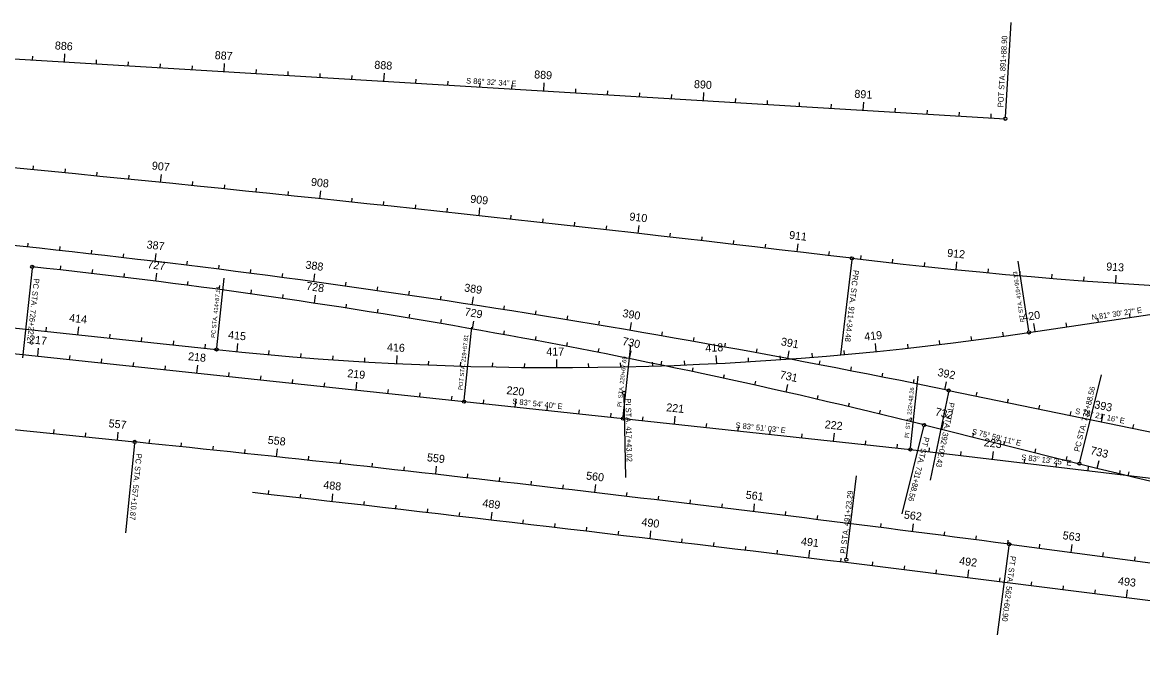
# Model space of a CAD drawing. Extents: x 919452 to 931278, y 583254 to 665650.
# Drawn here: x 927014 to 927714, y 636499 to 636895 of the extents above; entities that cross this region are included whole.
import ezdxf

# ---------------------------------------------------------------- set-up
doc = ezdxf.new("R2010")
doc.units = 0
for name, color, linetype in [('CLConst_dp', 7, 'Continuous'), ('CurveDataLabel_dp', 7, 'Continuous'), ('StationTicL_dp', 7, 'Continuous'), ('StationTicS_dp', 7, 'Continuous'), ('TextBLStation', 7, 'Continuous'), ('TextLabel', 7, 'Continuous')]:
    doc.layers.add(name, color=color, linetype=linetype)

msp = doc.modelspace()

# ---------------------------------------------------------------- linework, layer by layer
at = {"layer": 'CLConst_dp'}
for p, q in [((926993.81, 636873.2), (927628.09, 636834.88)), ((926652.85, 636742.2), (927135.36, 636690.73)), ((926651.16, 636726.29), (927289.95, 636658.15)), ((927642.87, 636701.38), (927761.55, 636719.1)), ((926620.06, 636680.55), (927084.21, 636632.96)), ((927592.72, 636665.12), (927788.61, 636624.75)), ((927289.95, 636658.15), (927389.26, 636647.56)), ((927389.26, 636647.56), (927568.79, 636628.21)), ((927577.33, 636643.56), (927674.36, 636619.34)), ((927568.79, 636628.21), (927746.27, 636607.13)), ((927630.5, 636569.05), (928164.62, 636498.82))]:
    msp.add_line(p, q, dxfattribs=at)
for centre, radius, start, end in [((924808.61, 613941.45), 22968.31, 83.189634, 85.623449), ((926386.43, 630812.14), 5976, 78.354474, 84.656985), ((927919.83, 639992.88), 3268.24, 263.18963, 272.20538), ((926584.51, 632665.58), 4100, 75.98637, 83.89999), ((927347.51, 638679.45), 2000, 263.91108, 278.49255), ((925121.35, 617487.67), 19245.65, 82.508751, 84.146229), ((928618.75, 640403.27), 3900, 255.98637, 261.64217), ((922956.96, 599413.81), 37423.99, 82.411957, 83.554939)]:
    msp.add_arc(centre, radius, start, end, dxfattribs=at)
at = {"layer": 'CurveDataLabel_dp'}
for p, q in [((927628.15, 636835.87), (927631.73, 636895.12)), ((927532.16, 636746.7), (927525.07, 636687.36)), ((927642.72, 636702.37), (927636.23, 636745.83)), ((927020.08, 636741.37), (927014.11, 636685.5)), ((927135.47, 636691.73), (927140.13, 636735.38)), ((927290.06, 636659.14), (927294.92, 636704.74)), ((927389.37, 636648.55), (927394.15, 636693.33)), ((927674.6, 636620.31), (927688.23, 636674.91)), ((927568.9, 636629.21), (927573.72, 636673.98)), ((927389.82, 636662.59), (927390.9, 636610.77)), ((927592.52, 636664.14), (927581.17, 636609.04)), ((927577.09, 636642.59), (927563.49, 636588.08)), ((927084.11, 636631.97), (927078.38, 636576.07)), ((927528.88, 636560.37), (927535.2, 636611.74)), ((927630.37, 636568.06), (927623.04, 636512.38))]:
    msp.add_line(p, q, dxfattribs=at)
for centre in [(927628.09, 636834.88), (927532.27, 636747.7), (927020.19, 636742.37), (927642.87, 636701.38), (927135.36, 636690.73), (927389.8, 636663.59), (927592.72, 636665.12), (927289.95, 636658.15), (927389.26, 636647.56), (927577.33, 636643.56), (927084.21, 636632.96), (927568.79, 636628.21), (927674.36, 636619.34), (927630.5, 636569.05), (927528.76, 636559.38)]:
    msp.add_circle(centre, 1, dxfattribs=at)
at = {"layer": 'StationTicL_dp'}
for p, q in [((927040.27, 636870.39), (927040.57, 636875.38)), ((927140.09, 636864.36), (927140.39, 636869.35)), ((927239.91, 636858.33), (927240.21, 636863.32)), ((927339.72, 636852.3), (927340.02, 636857.29)), ((927439.54, 636846.27), (927439.84, 636851.26)), ((927539.36, 636840.24), (927539.66, 636845.23)), ((927100.4, 636795.14), (927100.9, 636800.11)), ((927199.88, 636784.94), (927200.4, 636789.91)), ((927299.31, 636774.31), (927299.85, 636779.28)), ((927398.7, 636763.25), (927399.26, 636768.22)), ((927498.03, 636751.76), (927498.62, 636756.73)), ((927096.96, 636745.75), (927097.55, 636750.71)), ((927597.41, 636740.58), (927597.9, 636745.56)), ((927097.4, 636733.38), (927098.02, 636738.34)), ((927196.14, 636733.03), (927196.82, 636737.98)), ((927697.05, 636732.24), (927697.39, 636737.23)), ((927196.45, 636719.66), (927197.2, 636724.6)), ((927295.1, 636718.65), (927295.86, 636723.59)), ((927048.71, 636699.98), (927049.24, 636704.95)), ((927295.14, 636703.53), (927296, 636708.45)), ((927393.81, 636702.62), (927394.65, 636707.55)), ((927646.69, 636701.95), (927645.96, 636706.9)), ((927023.65, 636686.56), (927024.18, 636691.53)), ((927148.15, 636689.41), (927148.65, 636694.38)), ((927393.4, 636685), (927394.39, 636689.9)), ((927492.23, 636684.94), (927493.16, 636689.85)), ((927547.49, 636689.47), (927546.99, 636694.45)), ((927247.86, 636681.93), (927248.11, 636686.93)), ((927347.82, 636679.45), (927347.82, 636684.45)), ((927447.78, 636681.96), (927447.53, 636686.96)), ((927123.09, 636675.95), (927123.62, 636680.92)), ((927222.52, 636665.34), (927223.05, 636670.32)), ((927491.19, 636664.07), (927492.29, 636668.95)), ((927590.34, 636665.61), (927591.35, 636670.51)), ((927321.96, 636654.74), (927322.49, 636659.71)), ((927421.39, 636644.1), (927421.92, 636649.07)), ((927688.29, 636645.43), (927689.3, 636650.32)), ((927588.44, 636640.79), (927589.65, 636645.64)), ((927073.4, 636634.07), (927073.91, 636639.04)), ((927520.81, 636633.38), (927521.35, 636638.36)), ((927172.86, 636623.67), (927173.39, 636628.64)), ((927620.17, 636622.11), (927620.76, 636627.07)), ((927685.46, 636616.59), (927686.66, 636621.44)), ((927272.26, 636612.75), (927272.82, 636617.72)), ((927371.6, 636601.31), (927372.19, 636606.28)), ((927207.5, 636595.63), (927208.07, 636600.6)), ((927470.89, 636589.36), (927471.5, 636594.33)), ((927306.84, 636584.14), (927307.42, 636589.11)), ((927406.15, 636572.39), (927406.74, 636577.35)), ((927570.11, 636576.9), (927570.74, 636581.86)), ((927505.42, 636560.37), (927506.03, 636565.33)), ((927669.26, 636563.96), (927669.92, 636568.91)), ((927604.67, 636548.08), (927605.29, 636553.04)), ((927703.87, 636535.53), (927704.51, 636540.49))]:
    msp.add_line(p, q, dxfattribs=at)
at = {"layer": 'StationTicS_dp'}
for p, q in [((927020.31, 636871.59), (927020.46, 636874.09)), ((927060.23, 636869.18), (927060.38, 636871.68)), ((927080.2, 636867.98), (927080.35, 636870.47)), ((927100.16, 636866.77), (927100.31, 636869.27)), ((927120.12, 636865.56), (927120.27, 636868.06)), ((927160.05, 636863.15), (927160.2, 636865.65)), ((927180.01, 636861.95), (927180.17, 636864.44)), ((927199.98, 636860.74), (927200.13, 636863.24)), ((927219.94, 636859.53), (927220.09, 636862.03)), ((927259.87, 636857.12), (927260.02, 636859.62)), ((927279.83, 636855.92), (927279.98, 636858.41)), ((927299.8, 636854.71), (927299.95, 636857.2)), ((927319.76, 636853.5), (927319.91, 636856)), ((927359.69, 636851.09), (927359.84, 636853.59)), ((927379.65, 636849.89), (927379.8, 636852.38)), ((927399.61, 636848.68), (927399.76, 636851.17)), ((927419.58, 636847.47), (927419.73, 636849.97)), ((927459.5, 636845.06), (927459.66, 636847.56)), ((927479.47, 636843.85), (927479.62, 636846.35)), ((927499.43, 636842.65), (927499.58, 636845.14)), ((927519.4, 636841.44), (927519.55, 636843.94)), ((927559.32, 636839.03), (927559.47, 636841.53)), ((927579.29, 636837.82), (927579.44, 636840.32)), ((927599.25, 636836.62), (927599.4, 636839.11)), ((927619.21, 636835.41), (927619.36, 636837.91)), ((927020.78, 636802.98), (927021.02, 636805.47)), ((927040.69, 636801.04), (927040.93, 636803.53)), ((927060.59, 636799.09), (927060.84, 636801.58)), ((927080.5, 636797.12), (927080.74, 636799.61)), ((927120.3, 636793.13), (927120.55, 636795.62)), ((927140.2, 636791.11), (927140.45, 636793.6)), ((927160.09, 636789.07), (927160.35, 636791.56)), ((927179.99, 636787.01), (927180.24, 636789.5)), ((927219.77, 636782.85), (927220.03, 636785.34)), ((927239.66, 636780.74), (927239.92, 636783.23)), ((927259.54, 636778.62), (927259.81, 636781.1)), ((927279.43, 636776.47), (927279.7, 636778.96)), ((927319.19, 636772.14), (927319.47, 636774.62)), ((927339.07, 636769.94), (927339.35, 636772.43)), ((927358.95, 636767.73), (927359.23, 636770.21)), ((927378.82, 636765.5), (927379.1, 636767.98)), ((927418.57, 636760.99), (927418.85, 636763.47)), ((927438.44, 636758.71), (927438.72, 636761.19)), ((927458.31, 636756.41), (927458.59, 636758.89)), ((927017.46, 636754.73), (927017.73, 636757.21)), ((927037.35, 636752.58), (927037.62, 636755.07)), ((927057.22, 636750.37), (927057.5, 636752.85)), ((927478.17, 636754.09), (927478.46, 636756.58)), ((927517.9, 636749.41), (927518.19, 636751.89)), ((927077.09, 636748.09), (927077.38, 636750.58)), ((927116.81, 636743.34), (927117.12, 636745.82)), ((927537.76, 636747.05), (927538.05, 636749.53)), ((927557.63, 636744.77), (927557.9, 636747.25)), ((927577.51, 636742.61), (927577.77, 636745.1)), ((927037.82, 636740.45), (927038.09, 636742.93)), ((927057.69, 636738.19), (927057.98, 636740.67)), ((927077.55, 636735.83), (927077.85, 636738.31)), ((927136.66, 636740.86), (927136.97, 636743.34)), ((927156.49, 636738.32), (927156.82, 636740.79)), ((927176.32, 636735.7), (927176.65, 636738.18)), ((927617.31, 636738.67), (927617.55, 636741.16)), ((927637.23, 636736.88), (927637.45, 636739.37)), ((927657.16, 636735.21), (927657.37, 636737.7)), ((927117.23, 636730.83), (927117.56, 636733.31)), ((927137.06, 636728.18), (927137.4, 636730.66)), ((927215.95, 636730.28), (927216.3, 636732.76)), ((927677.1, 636733.66), (927677.29, 636736.16)), ((927156.87, 636725.44), (927157.22, 636727.91)), ((927176.67, 636722.6), (927177.03, 636725.07)), ((927235.76, 636727.48), (927236.11, 636729.95)), ((927255.55, 636724.6), (927255.91, 636727.07)), ((927275.33, 636721.66), (927275.7, 636724.13)), ((927216.22, 636716.63), (927216.6, 636719.1)), ((927314.86, 636715.58), (927315.25, 636718.05)), ((927235.97, 636713.5), (927236.37, 636715.96)), ((927255.71, 636710.27), (927256.12, 636712.74)), ((927275.43, 636706.95), (927275.85, 636709.41)), ((927334.62, 636712.44), (927335.01, 636714.9)), ((927354.36, 636709.23), (927354.76, 636711.7)), ((927686.26, 636707.86), (927685.89, 636710.33)), ((927706.04, 636710.81), (927705.67, 636713.28)), ((927028.83, 636702.1), (927029.09, 636704.58)), ((927314.83, 636700.01), (927315.27, 636702.47)), ((927374.09, 636705.96), (927374.5, 636708.42)), ((927666.48, 636704.9), (927666.11, 636707.38)), ((927068.6, 636697.85), (927068.87, 636700.34)), ((927088.49, 636695.73), (927088.75, 636698.22)), ((927108.37, 636693.61), (927108.64, 636696.1)), ((927334.5, 636696.4), (927334.96, 636698.86)), ((927354.15, 636692.7), (927354.62, 636695.15)), ((927413.52, 636699.21), (927413.95, 636701.68)), ((927433.21, 636695.74), (927433.65, 636698.21)), ((927587.24, 636693.87), (927586.94, 636696.35)), ((927607.09, 636696.37), (927606.76, 636698.84)), ((927626.9, 636699.06), (927626.56, 636701.54)), ((927128.26, 636691.49), (927128.53, 636693.98)), ((927168.06, 636687.52), (927168.29, 636690)), ((927187.99, 636685.82), (927188.19, 636688.31)), ((927373.79, 636688.9), (927374.27, 636691.35)), ((927452.9, 636692.21), (927453.34, 636694.67)), ((927472.57, 636688.61), (927473.02, 636691.06)), ((927507.65, 636685.87), (927507.45, 636688.36)), ((927527.58, 636687.57), (927527.35, 636690.06)), ((927567.38, 636691.57), (927567.1, 636694.06)), ((927043.54, 636684.44), (927043.8, 636686.92)), ((927063.42, 636682.32), (927063.69, 636684.8)), ((927083.31, 636680.19), (927083.58, 636682.68)), ((927207.94, 636684.32), (927208.11, 636686.82)), ((927227.89, 636683.03), (927228.04, 636685.52)), ((927267.84, 636681.04), (927267.94, 636683.53)), ((927287.83, 636680.34), (927287.91, 636682.84)), ((927307.82, 636679.84), (927307.87, 636682.34)), ((927327.82, 636679.55), (927327.85, 636682.05)), ((927367.82, 636679.55), (927367.8, 636682.05)), ((927387.82, 636679.86), (927387.77, 636682.35)), ((927407.81, 636680.36), (927407.74, 636682.86)), ((927413, 636681), (927413.51, 636683.45)), ((927427.8, 636681.06), (927427.7, 636683.56)), ((927467.75, 636683.07), (927467.6, 636685.56)), ((927487.71, 636684.37), (927487.53, 636686.86)), ((927511.88, 636681.2), (927512.35, 636683.66)), ((927103.2, 636678.07), (927103.46, 636680.56)), ((927142.97, 636673.83), (927143.24, 636676.32)), ((927162.86, 636671.71), (927163.12, 636674.19)), ((927432.58, 636676.91), (927433.09, 636679.36)), ((927452.14, 636672.73), (927452.66, 636675.17)), ((927531.52, 636677.4), (927531.99, 636679.86)), ((927551.14, 636673.54), (927551.63, 636675.99)), ((927182.75, 636669.59), (927183.01, 636672.07)), ((927202.63, 636667.47), (927202.9, 636669.95)), ((927471.67, 636668.45), (927472.21, 636670.89)), ((927570.75, 636669.61), (927571.24, 636672.06)), ((927242.41, 636663.22), (927242.67, 636665.71)), ((927262.3, 636661.1), (927262.56, 636663.59)), ((927282.18, 636658.98), (927282.45, 636661.47)), ((927510.68, 636659.6), (927511.25, 636662.04)), ((927609.93, 636661.58), (927610.44, 636664.02)), ((927302.07, 636656.86), (927302.33, 636659.34)), ((927341.84, 636652.61), (927342.11, 636655.1)), ((927530.15, 636655.04), (927530.73, 636657.47)), ((927629.52, 636657.54), (927630.03, 636659.99)), ((927649.11, 636653.5), (927649.61, 636655.95)), ((927361.73, 636650.49), (927362, 636652.98)), ((927381.62, 636648.37), (927381.88, 636650.86)), ((927401.5, 636646.24), (927401.77, 636648.72)), ((927549.6, 636650.38), (927550.19, 636652.81)), ((927569.03, 636645.62), (927569.63, 636648.05)), ((927668.7, 636649.46), (927669.2, 636651.91)), ((927033.61, 636638.15), (927033.86, 636640.64)), ((927441.27, 636641.95), (927441.54, 636644.44)), ((927461.16, 636639.81), (927461.43, 636642.3)), ((927481.04, 636637.67), (927481.31, 636640.15)), ((927707.87, 636641.39), (927708.38, 636643.84)), ((927053.5, 636636.11), (927053.76, 636638.6)), ((927093.3, 636632.03), (927093.55, 636634.52)), ((927113.19, 636629.97), (927113.45, 636632.46)), ((927500.93, 636635.53), (927501.2, 636638.01)), ((927540.7, 636631.24), (927540.97, 636633.73)), ((927607.84, 636635.95), (927608.45, 636638.37)), ((927627.25, 636631.1), (927627.85, 636633.53)), ((927133.08, 636627.89), (927133.34, 636630.38)), ((927152.97, 636625.79), (927153.23, 636628.27)), ((927560.58, 636629.1), (927560.85, 636631.58)), ((927580.45, 636626.83), (927580.75, 636629.31)), ((927600.31, 636624.47), (927600.61, 636626.95)), ((927646.65, 636626.26), (927647.26, 636628.69)), ((927192.74, 636621.52), (927193.01, 636624.01)), ((927212.62, 636619.36), (927212.9, 636621.85)), ((927232.5, 636617.18), (927232.78, 636619.66)), ((927640.04, 636619.75), (927640.33, 636622.23)), ((927659.9, 636617.39), (927660.19, 636619.87)), ((927666.06, 636621.42), (927666.66, 636623.84)), ((927252.38, 636614.97), (927252.66, 636617.46)), ((927292.13, 636610.5), (927292.41, 636612.99)), ((927679.76, 636615.03), (927680.05, 636617.51)), ((927699.62, 636612.67), (927699.91, 636615.15)), ((927704.9, 636611.85), (927705.48, 636614.28)), ((927312, 636608.24), (927312.29, 636610.72)), ((927331.87, 636605.95), (927332.16, 636608.43)), ((927351.74, 636603.64), (927352.03, 636606.13)), ((927167.76, 636600.16), (927168.04, 636602.64)), ((927187.63, 636597.9), (927187.92, 636600.38)), ((927391.46, 636598.97), (927391.76, 636601.45)), ((927411.32, 636596.6), (927411.62, 636599.08)), ((927227.37, 636593.36), (927227.66, 636595.84)), ((927247.24, 636591.07), (927247.53, 636593.55)), ((927267.11, 636588.77), (927267.4, 636591.25)), ((927431.18, 636594.21), (927431.48, 636596.69)), ((927451.03, 636591.8), (927451.34, 636594.28)), ((927286.98, 636586.46), (927287.27, 636588.95)), ((927326.71, 636581.81), (927327, 636584.3)), ((927490.74, 636586.91), (927491.04, 636589.39)), ((927510.58, 636584.44), (927510.89, 636586.92)), ((927530.43, 636581.95), (927530.74, 636584.43)), ((927346.57, 636579.47), (927346.86, 636581.96)), ((927366.43, 636577.12), (927366.72, 636579.6)), ((927386.29, 636574.76), (927386.59, 636577.24)), ((927550.27, 636579.43), (927550.58, 636581.91)), ((927589.94, 636574.34), (927590.26, 636576.82)), ((927426.01, 636570), (927426.3, 636572.49)), ((927445.86, 636567.61), (927446.16, 636570.09)), ((927609.78, 636571.77), (927610.1, 636574.25)), ((927629.61, 636569.17), (927629.93, 636571.65)), ((927465.72, 636565.21), (927466.02, 636567.69)), ((927485.57, 636562.79), (927485.87, 636565.27)), ((927649.44, 636566.56), (927649.76, 636569.04)), ((927689.09, 636561.35), (927689.42, 636563.83)), ((927525.27, 636557.93), (927525.58, 636560.41)), ((927545.12, 636555.48), (927545.43, 636557.96)), ((927564.97, 636553.03), (927565.28, 636555.51)), ((927708.92, 636558.74), (927709.25, 636561.22)), ((927584.82, 636550.56), (927585.13, 636553.04)), ((927624.51, 636545.59), (927624.82, 636548.07)), ((927644.35, 636543.09), (927644.67, 636545.57)), ((927664.2, 636540.58), (927664.51, 636543.06)), ((927684.04, 636538.06), (927684.35, 636540.54))]:
    msp.add_line(p, q, dxfattribs=at)

# ---------------------------------------------------------------- texts
at = {"layer": 'CurveDataLabel_dp'}
for s, height, rotation, p in [('POT STA. 891+88.90', 3.5, 86.54273, (927626.77, 636841.97)), ('PRC STA. 911+34.48', 3.5, 263.18963, (927533.18, 636740.54)), ('PT STA. 419+96.13', 2.625, 98.49255, (927640.1, 636708.04)), ('PC STA. 726+22.27', 3.5, 263.89999, (927021.19, 636735.22)), ('PC STA. 414+87.14', 2.625, 83.91108, (927134.36, 636697.88)), ('POT STA. 219+67.81', 2.625, 83.91108, (927288.96, 636665.3)), ('PI  STA. 220+67.69', 2.625, 83.91108, (927388.26, 636654.7)), ('PC STA. 732+88.56', 3.5, 75.98637, (927674.35, 636626.56)), ('PI  STA. 222+48.26', 2.625, 83.8509, (927567.8, 636635.36)), ('PI STA. 417+43.02', 3.5, 271.20181, (927390.74, 636660.11)), ('PT STA. 392+02.43', 3.5, 258.35447, (927593.02, 636657.91)), ('PT STA. 731+88.56', 3.5, 255.98637, (927577.34, 636636.34)), ('PC STA. 557+10.87', 3.5, 264.14623, (927085.24, 636625.82)), ('PI STA. 491+23.29', 3.5, 82.98345, (927528.32, 636562.96)), ('PT STA. 562+60.90', 3.5, 262.50875, (927631.32, 636561.89))]:
    msp.add_text(s, height=height, rotation=rotation, dxfattribs=at).set_placement(p)
at = {"layer": 'TextBLStation'}
for s, rotation, p in [('886', 356.54273, (927034.2, 636878.27)), ('887', 356.54273, (927134.08, 636872.23)), ('888', 356.54273, (927233.8, 636866.21)), ('889', 356.54273, (927333.65, 636860.18)), ('890', 356.54273, (927433.48, 636854.15)), ('891', 356.54273, (927533.69, 636848.09)), ('907', 354.27347, (927094.71, 636803.24)), ('908', 354.02401, (927194.12, 636793.08)), ('909', 353.77456, (927293.63, 636782.48)), ('910', 353.5251, (927393.06, 636771.44)), ('387', 353.17159, (927091.42, 636753.96)), ('911', 353.27565, (927492.82, 636759.93)), ('912', 354.33827, (927591.59, 636748.69)), ('727', 352.81375, (927091.91, 636741.63)), ('388', 352.21282, (927190.65, 636741.35)), ('913', 356.09138, (927690.99, 636740.17)), ('728', 351.41629, (927191.07, 636728.06)), ('389', 351.25406, (927289.79, 636727.06)), ('729', 350.01883, (927290, 636712.05)), ('414', 353.91108, (927043.06, 636708.12)), ('390', 350.29529, (927388.64, 636711.11)), ('420', 8.49255, (927639.14, 636708.4)), ('415', 354.27948, (927142.37, 636697.53)), ('419', 5.73863, (927540.24, 636696.28)), ('217', 353.91108, (927018.01, 636694.7)), ('730', 348.62138, (927388.49, 636693.64)), ('391', 349.33653, (927487.59, 636693.44)), ('218', 353.91108, (927117.35, 636684.11)), ('416', 357.14426, (927241.71, 636689.75)), ('417', 0.00905, (927341.35, 636686.95)), ('418', 2.87384, (927440.84, 636689.13)), ('219', 353.91108, (927216.82, 636673.49)), ('731', 347.22392, (927486.86, 636672.75)), ('392', 348.37776, (927585.41, 636674.29)), ('220', 353.91108, (927316.27, 636662.89)), ('221', 353.8509, (927416.09, 636652.21)), ('732', 345.98637, (927583.86, 636649.66)), ('393', 348.35447, (927683.35, 636654.1)), ('557', 354.14623, (927067.73, 636642.19)), ('222', 353.8509, (927515.07, 636641.55)), ('558', 353.88088, (927167.12, 636631.82)), ('223', 353.22367, (927614.52, 636630.33)), ('559', 353.58318, (927266.6, 636620.93)), ('733', 346.15448, (927680.86, 636625.45)), ('560', 353.28547, (927366, 636609.53)), ('488', 353.47839, (927201.83, 636603.83)), ('561', 352.98776, (927465.71, 636597.56)), ('489', 353.32529, (927301.22, 636592.35)), ('490', 353.17219, (927400.56, 636580.61)), ('562', 352.69005, (927564.53, 636585.18)), ('563', 352.50875, (927663.71, 636572.25)), ('491', 353.01909, (927500.24, 636568.56)), ('492', 352.86599, (927599.06, 636556.34)), ('493', 352.71289, (927698.29, 636543.8))]:
    msp.add_text(s, height=5, rotation=rotation, dxfattribs=at).set_placement(p)
at = {"layer": 'TextLabel'}
for s, rotation, p in [('S 86%%d 32\' 34" E', 356.54273, (927291.17, 636856.98)), ('N 81%%d 30\' 27" E', 8.49255, (927682.28, 636709.03)), ('S 83%%d 54\' 40" E', 353.91108, (927319.98, 636656.71)), ('S 78%%d 21\' 16" E', 348.35447, (927671.5, 636650.67)), ('S 83%%d 51\' 03" E', 353.8509, (927459.41, 636641.76)), ('S 75%%d 59\' 11" E', 345.98637, (927606.94, 636637.97)), ('S 83%%d 13\' 25" E', 353.22367, (927637.95, 636621.76))]:
    msp.add_text(s, height=3.5, rotation=rotation, dxfattribs=at).set_placement(p)

doc.saveas('drawing.dxf')
